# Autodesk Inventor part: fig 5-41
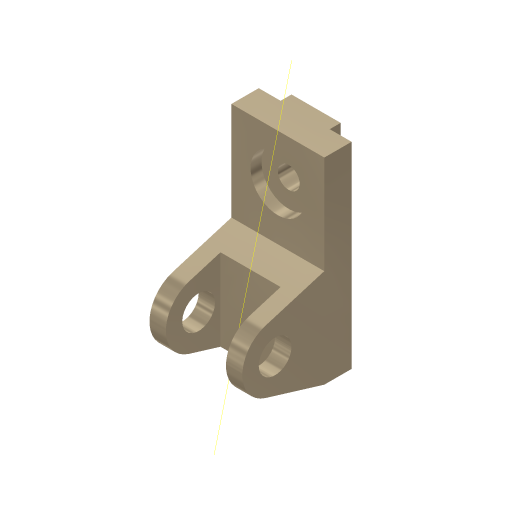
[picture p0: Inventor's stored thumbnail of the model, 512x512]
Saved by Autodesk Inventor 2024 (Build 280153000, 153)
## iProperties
Shininess: 65.0
Angle Display Precision: 2
Document Length Units: 11269
Document Angle Units: 11279
Document Time Units: 11290
Document Mass Units: 11283
Document Length Units Precision: 3
Document Angle Units Precision: 2
Created: 2001-11
Part Number: fig 5-41
Document SubType Name: Modeling
Designer: Renu Muthoo
Density: 1 g/cm^3
Material: Generic
Appearance: Metal-Titanium (Polished)
Density: 0.0
Volumn: 0.0
Area: 0.0
PropertySet Name: Model Information
Control State: 0
Master: False
Checked Out: False
Author: Renu Muthoo
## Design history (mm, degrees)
sketch "Sketch2"
  geometry: L1 (33.257, 104.664)-(33.257, -75.336); L2 (33.257, -75.336)-(8.257, -75.336); L3 (8.257, -75.336)-(-45.451, -59.045); L4 (-45.451, -1.628)-(8.257, 14.664); L5 (8.257, 14.664)-(8.257, 104.664); L6 (8.257, 104.664)-(33.257, 104.664); C1 r 15 at (-36.743, -30.336); A1 r 30 centre (-36.743, -30.336) between (-45.451, -1.628) and (-45.451, -59.045)
  constraints: 12 end point, 2 centre point, 2 equal length, 2 parallel, 2 point on circle, 2 tangent, 1 coincident, 1 perpendicular, 1 vertical
  dimensions: "d0" = 180 distance of L1.start L1.end; "d1" = 30 radius of A1; "d2" = 25 distance of L5.end L1.start; "d3" = 45 distance from line of L2 A1.centre; "d4" = 70 distance from line of L1 A1.centre; "d5" = 30 diameter of C1
extrude "Extrusion1" new body sketch "Sketch2" distance "d6" = 85; taper "d7" = 0 deg
workplane "Work Plane1"
sketch "Sketch3"
  geometry: L1 (15, 62.364)-(70, 62.364); L2 (70, 62.364)-(70, -52.386); L3 (70, -52.386)-(15, -52.386); L4 (15, -52.386)-(15, 62.364); L5 (0, -45)-(0, -28.708) reference
  constraints: 8 end point, 2 parallel, 1 horizontal, 1 perpendicular
  dimensions: "d8" = 55 distance of L1.start L1.end; "d9" = 15 distance between parallel lines of L5 L4
extrude "Extrusion2" cut sketch "Sketch3" distance "d10" = 50; taper "d11" = 0 deg
sketch "Sketch4"
  geometry: L1 (0, 25)-(85, 25) reference; L2 (0, 0)-(0, 25) reference; L3 (20, 25)-(65, 25); L4 (65, 25)-(65, 35); L5 (65, 35)-(20, 35); L6 (20, 35)-(20, 25)
  constraints: 8 end point, 2 parallel, 1 horizontal, 1 perpendicular, 1 point on line
  dimensions: "d12" = 45 distance of L4.end L5.end; "d13" = 10 distance of L3.end L4.end; "d14" = 20 distance between parallel lines of L2 L6
extrude "Extrusion3" join sketch "Sketch4" stored distance "d15" = 50; taper "d16" = 0 deg
sketch "Sketch5"
  geometry: L1 (85, 0)-(85, 90) reference; L2 (0, 90)-(85, 90) reference; 1 further point
  dimensions: "d17" = 42 distance from line of L2 point (42.5, 48); "d18" = 42.5 distance from line of L1 point (42.5, 48)
hole "Hole1" sketch "Sketch5" diameter "d19" = 20; stored, may be unused: countersink angle "d23" = 82 deg, drill point angle "d25" = 118 deg; dims "d20" = 6, "d21" = 50, "d22" = 10, "d24" = 8
workaxis "Work Axis1"
body "Solid1"
node "Sketch1"
